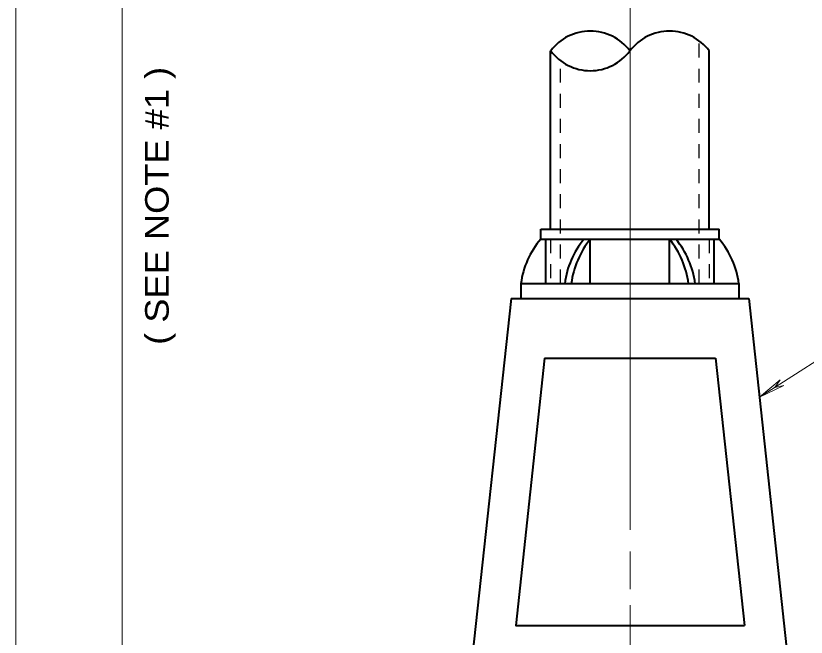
# Model space of a CAD drawing. Extents: x 312583 to 312854, y 144419 to 144597.
# Drawn here: x 312676.49 to 312701.98, y 144464.15 to 144484.18 of the extents above; entities that cross this region are included whole.
import ezdxf

# ---------------------------------------------------------------- set-up
doc = ezdxf.new("R2010")
doc.units = 0
doc.header["$LTSCALE"] = 0.3
doc.linetypes.add('SHORT_DASHED', pattern=[2.7, 1.5, -1.2])
doc.layers.add('1', color=7, linetype='Continuous', lineweight=40)
doc.layers.add('2', color=7, linetype='Continuous', lineweight=13)

msp = doc.modelspace()

# ---------------------------------------------------------------- linework, layer by layer
at = {"layer": '1', "lineweight": 13}
for p, q in [((312696.2997, 144487.0309), (312696.2997, 144467.6036)), ((312696.2997, 144466.9136), (312696.2997, 144465.6946)), ((312696.2997, 144465.1733), (312696.2997, 144450.3076))]:
    msp.add_line(p, q, dxfattribs=at)
at = {"layer": '1', "linetype": 'SHORT_DASHED', "lineweight": 25}
for p, q in [((312698.5307, 144475.5463), (312698.5307, 144483.3739)), ((312694.061, 144475.5463), (312694.061, 144482.7299)), ((312693.739, 144476.9799), (312693.739, 144475.5463)), ((312698.8527, 144476.9799), (312698.8527, 144475.5463))]:
    msp.add_line(p, q, dxfattribs=at)
at = {"layer": '1'}
for p, q in [((312693.739, 144477.3019), (312693.739, 144483.0519)), ((312698.8527, 144477.3019), (312698.8527, 144483.0519)), ((312693.4247, 144477.3019), (312699.1747, 144477.3019)), ((312693.4247, 144476.9799), (312693.4247, 144477.3019)), ((312699.1747, 144476.9799), (312699.1747, 144477.3019)), ((312693.4247, 144476.9799), (312699.1747, 144476.9799)), ((312693.5857, 144475.5463), (312693.5857, 144476.9799)), ((312695.0193, 144475.5463), (312695.0193, 144476.9799)), ((312697.5723, 144475.5463), (312697.5723, 144476.9799)), ((312699.0137, 144475.5463), (312699.0137, 144476.9799)), ((312692.7807, 144475.5463), (312699.811, 144475.5463)), ((312692.7807, 144475.5463), (312692.7807, 144475.0633)), ((312699.811, 144475.5463), (312699.811, 144475.0633)), ((312692.4663, 144475.0633), (312691.186, 144463.2489)), ((312692.4663, 144475.0633), (312700.133, 144475.0633)), ((312700.133, 144475.0633), (312701.4057, 144463.2489)), ((312693.5397, 144473.1466), (312699.052, 144473.1466)), ((312699.052, 144473.1466), (312699.9873, 144464.5216))]:
    msp.add_line(p, q, dxfattribs=at)
msp.add_lwpolyline([(312693.5397, 144473.1466), (312692.612, 144464.5216), (312699.9873, 144464.5216)], dxfattribs=at)
for centre, radius, start, end in [((312695.0193, 144482.0923), 1.5972, 36.8699, 143.1301), ((312697.5749, 144482.0923), 1.5972, 36.8699, 143.1301), ((312695.0193, 144484.009), 1.5972, 216.8699, 323.1301), ((312695.4643, 144475.2129), 2.7014, 139.11, 172.96502), ((312697.0124, 144475.1755), 2.8438, 140.58204, 172.56057), ((312697.3094, 144475.1545), 2.9293, 141.42192, 172.36542), ((312695.2849, 144475.1545), 2.9293, 7.63457, 38.57808), ((312695.5818, 144475.1755), 2.8438, 7.43942, 39.41796), ((312697.1299, 144475.2129), 2.7014, 7.03498, 40.89)]:
    msp.add_arc(centre, radius, start, end, dxfattribs=at)
at = {"layer": '2'}
for p, q in [((312676.489, 144460.8033), (312676.489, 144496.2769)), ((312679.916, 144461.9686), (312679.916, 144491.9989)), ((312700.478, 144471.8816), (312703.1997, 144473.6373)), ((312700.478, 144471.8816), (312701.145, 144472.4413)), ((312700.478, 144471.8816), (312701.26, 144472.2573)), ((312701.145, 144472.4413), (312700.9687, 144472.1959)), ((312701.26, 144472.2573), (312700.9687, 144472.1959))]:
    msp.add_line(p, q, dxfattribs=at)

# ---------------------------------------------------------------- texts
at = {"layer": '2', "width": 1.15}
msp.add_text('( SEE NOTE #1 )', height=0.76, rotation=90, dxfattribs=at).set_placement((312681.4195, 144473.572))

doc.saveas('drawing.dxf')
